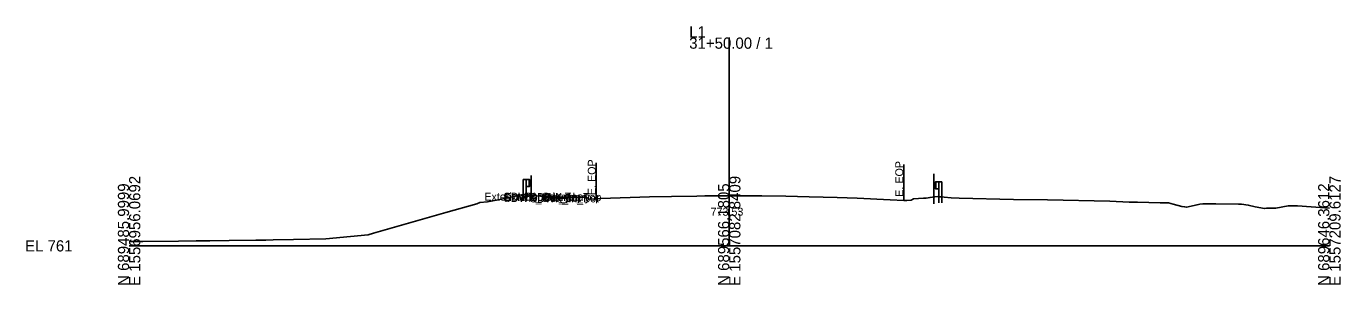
# Model space of a CAD drawing. Extents: x -26 to 2603, y -3010 to 9589.
# Drawn here: x 974.3 to 1302.8, y 4990.3 to 5054.8 of the extents above; entities that cross this region are included whole.
import ezdxf

# ---------------------------------------------------------------- set-up
doc = ezdxf.new("R2010")
doc.units = 0
for name, color, linetype in [('Default', 7, 'Continuous'), ('Exist Cross Section Cell', 7, 'Continuous'), ('Exist XS Center Line Elevation Label', 7, 'Continuous'), ('Exist XS Ground Line', 7, 'Continuous'), ('Prop CMT Conc Surface', 7, 'Continuous'), ('Prop CMT Concrete Structures', 7, 'Continuous'), ('Prop XS Earthwork Shape', 7, 'Continuous'), ('Prop XS Label Text', 7, 'Continuous'), ('Scratch_Level_1', 7, 'Continuous'), ('Typical Guardrail CELL', 7, 'Continuous')]:
    doc.layers.add(name, color=color, linetype=linetype)

msp = doc.modelspace()

# ---------------------------------------------------------------- linework, layer by layer
at = {"layer": 'Exist Cross Section Cell'}
for p, q in [((1150, 5000), (1150, 5052.04)), ((1000, 5000), (1150, 5000)), ((1150, 5000), (1300, 5000))]:
    msp.add_line(p, q, dxfattribs=at)
at = {"layer": 'Exist XS Ground Line'}
msp.add_lwpolyline([(1000, 5001.1), (1000.51, 5001.08), (1003.42, 5001.1), (1012.37, 5001.2), (1016.8, 5001.24), (1018.07, 5001.26), (1019.02, 5001.25), (1020.2, 5001.26), (1025.01, 5001.33), (1031.72, 5001.43), (1034.2, 5001.44), (1036.05, 5001.51), (1041.07, 5001.57), (1049.16, 5001.74), (1055.36, 5002.37), (1059.73, 5002.79), (1061.13, 5003.18), (1064.62, 5004.19), (1079.16, 5008.33), (1086.88, 5010.53), (1087.65, 5010.82), (1089.58, 5011), (1092.27, 5011.53), (1098.52, 5012.86), (1100.96, 5012.59), (1103.77, 5012.31), (1109.35, 5012.2), (1113.13, 5012.14), (1114.3, 5012.13), (1114.9, 5011.68), (1116.3, 5011.74), (1116.76, 5011.77), (1117.95, 5011.81), (1130.04, 5012.23), (1135.6, 5012.34), (1141.93, 5012.45), (1143.94, 5012.48), (1146.22, 5012.51), (1149.22, 5012.52), (1150, 5012.53), (1151.67, 5012.53), (1155.03, 5012.51), (1158.15, 5012.48), (1164.17, 5012.38), (1169.97, 5012.27), (1176.95, 5012.06), (1181.94, 5011.9), (1190.2, 5011.51), (1193.61, 5011.36), (1194.41, 5011.35), (1195.44, 5011.41), (1196.05, 5011.79), (1198.6, 5011.9), (1199.19, 5011.92), (1200.22, 5012.1), (1201.98, 5012.32), (1205.48, 5011.98), (1207.5, 5011.89), (1221.06, 5011.61), (1229.56, 5011.54), (1245.11, 5011.18), (1249.94, 5010.95), (1252.02, 5010.91), (1257.73, 5010.79), (1259.83, 5010.72), (1260.98, 5010.38), (1263.14, 5009.87), (1263.84, 5009.72), (1264.32, 5009.65), (1266.95, 5010.28), (1267.63, 5010.4), (1268.37, 5010.52), (1271.65, 5010.51), (1277.28, 5010.43), (1278.04, 5010.38), (1279.72, 5010.18), (1281.49, 5009.74), (1283.79, 5009.32), (1284.31, 5009.41), (1284.77, 5009.44), (1286.61, 5009.41), (1289.73, 5010), (1290.16, 5009.99), (1292.08, 5010), (1300, 5009.43)], dxfattribs=at)
at = {"layer": 'Prop CMT Conc Surface'}
msp.add_line((1109.66, 5012.19), (1104.66, 5012.29), dxfattribs=at)
at = {"layer": 'Prop CMT Concrete Structures'}
msp.add_line((1109.66, 5011.86), (1104.66, 5011.96), dxfattribs=at)
for points in [[(1104.66, 5011.96), (1104.66, 5012.29)], [(1109.66, 5012.19), (1109.66, 5011.86)]]:
    msp.add_lwpolyline(points, dxfattribs=at)
at = {"layer": 'Prop XS Earthwork Shape'}
msp.add_lwpolyline([(1104.66, 5011.96), (1104.66, 5012.29), (1109.35, 5012.2), (1109.66, 5012.19), (1109.66, 5011.86)], close=True, dxfattribs=at)
at = {"layer": 'Prop XS Label Text'}
for p, q in [((1116.76, 5020.77), (1116.76, 5011.77)), ((1193.61, 5020.36), (1193.61, 5011.36))]:
    msp.add_line(p, q, dxfattribs=at)
at = {"layer": 'Scratch_Level_1'}
for p, q in [((1100.48, 5017.6), (1100.48, 5011.58)), ((1201.18, 5017.98), (1201.18, 5010.47))]:
    msp.add_line(p, q, dxfattribs=at)
at = {"layer": 'Typical Guardrail CELL'}
for p, q in [((1099.25, 5016.59), (1098.5, 5016.59)), ((1098.5, 5016.59), (1098.5, 5012.86)), ((1099.25, 5016.59), (1099.25, 5012.86)), ((1099.25, 5016.59), (1100, 5016.59)), ((1099.25, 5014.85), (1100, 5014.85)), ((1100, 5016.59), (1100, 5014.85)), ((1100, 5016.59), (1100.43, 5016.28)), ((1100, 5015.79), (1100.43, 5016.09)), ((1100, 5015.72), (1100, 5015.79)), ((1100, 5015.72), (1100, 5015.65)), ((1100, 5015.65), (1100.43, 5015.34)), ((1100, 5014.85), (1100.43, 5015.15)), ((1201.68, 5015.99), (1201.25, 5015.69)), ((1201.68, 5015.19), (1201.25, 5015.5)), ((1201.68, 5015.05), (1201.25, 5014.75)), ((1201.68, 5014.25), (1201.25, 5014.56)), ((1202.43, 5015.99), (1201.68, 5015.99)), ((1201.68, 5015.99), (1201.68, 5014.25)), ((1201.68, 5015.12), (1201.68, 5015.19)), ((1201.68, 5015.12), (1201.68, 5015.05)), ((1202.43, 5014.25), (1201.68, 5014.25)), ((1202.43, 5015.99), (1202.43, 5012.27)), ((1202.43, 5015.99), (1203.18, 5015.99)), ((1203.18, 5015.99), (1203.18, 5012.27)), ((1099.25, 5012.86), (1098.5, 5012.86)), ((1098.5, 5012.86), (1098.5, 5011.35)), ((1099.25, 5012.86), (1099.25, 5011.35)), ((1202.43, 5012.27), (1203.18, 5012.27)), ((1202.43, 5012.27), (1202.43, 5010.75)), ((1203.18, 5012.27), (1203.18, 5010.75))]:
    msp.add_line(p, q, dxfattribs=at)
for centre, start, end in [((1100.36, 5016.19), 304.9888, 54.997), ((1100.36, 5015.25), 304.9634, 54.9941), ((1201.32, 5015.59), 125.003, 235.0112), ((1201.32, 5014.65), 125.0059, 235.0366)]:
    msp.add_arc(centre, 0.116, start, end, dxfattribs=at)

# ---------------------------------------------------------------- texts
at = {"layer": 'Default'}
for s, height, p in [('Exterior Boundary', 2, (1088.8, 5011.29)), ('SDWK_Out_Top', 2, (1093.59, 5011.29)), ('SDWK_Out_Bot', 2, (1093.62, 5010.96)), ('Exterior Boundary', 2, (1093.8, 5011.19)), ('SDWK_In_Top', 2, (1100.21, 5011.19)), ('SDWK_In_Bot', 2, (1100.24, 5010.86)), ('-', 0.0001, (1000, 5000))]:
    msp.add_text(s, height=height, dxfattribs=at).set_placement(p)
at = {"layer": 'Exist Cross Section Cell'}
for s, p in [('L1', (1140, 5052.04)), ('31+50.00 / 1', (1140, 5049.24)), ('EL 761', (974, 4998.6))]:
    msp.add_text(s, height=2.8, dxfattribs=at).set_placement(p)
for s, p in [('E 1556956.0692', (1002.8, 4990)), ('E 1557082.8409', (1152.8, 4990)), ('E 1557209.6127', (1302.8, 4990)), ('N 689485.9999', (1000, 4990)), ('N 689566.1805', (1150, 4990)), ('N 689646.3612', (1300, 4990))]:
    msp.add_text(s, height=2.8, rotation=90, dxfattribs=at).set_placement(p)
at = {"layer": 'Exist XS Center Line Elevation Label'}
msp.add_text('773.53', height=2, dxfattribs=at).set_placement((1145.35, 5007.53))
at = {"layer": 'Prop XS Label Text'}
for p in [(1116.66, 5012.69), (1193.51, 5012.28)]:
    msp.add_text('E. EOP', height=2, rotation=90, dxfattribs=at).set_placement(p)

doc.saveas('drawing.dxf')
